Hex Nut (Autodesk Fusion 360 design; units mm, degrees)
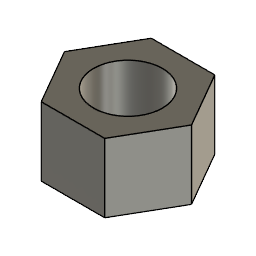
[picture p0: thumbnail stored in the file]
part number: 2025-12-16-11-09-20-013
sketch "Sketch1" plane through (0, 0, 0) normal (0, 0, 1) x axis (1, 0, 0)
  line L1 (-4.6188, 0) -> (-2.3094, 4)
  line L2 (-2.3094, -4) -> (-4.6188, 0)
  line L3 (2.3094, -4) -> (-2.3094, -4)
  line L4 (4.6188, 0) -> (2.3094, -4)
  line L5 (2.3094, 4) -> (4.6188, 0)
  line L6 (-2.3094, 4) -> (2.3094, 4)
  circle C1 centre (0, 0) radius 2.5
  point P1 (0, 0)
  point P2 (0, 0)
  point P9 (0, 0)
  coincident P1 P2
  coincident P1 P9
  horizontal L6
  dimension "d1" diameter C1 = 5
  dimension "d2" distance L3 L6 = 8
extrude "Extrude1" new body sketch "Sketch1" along normal blind 5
